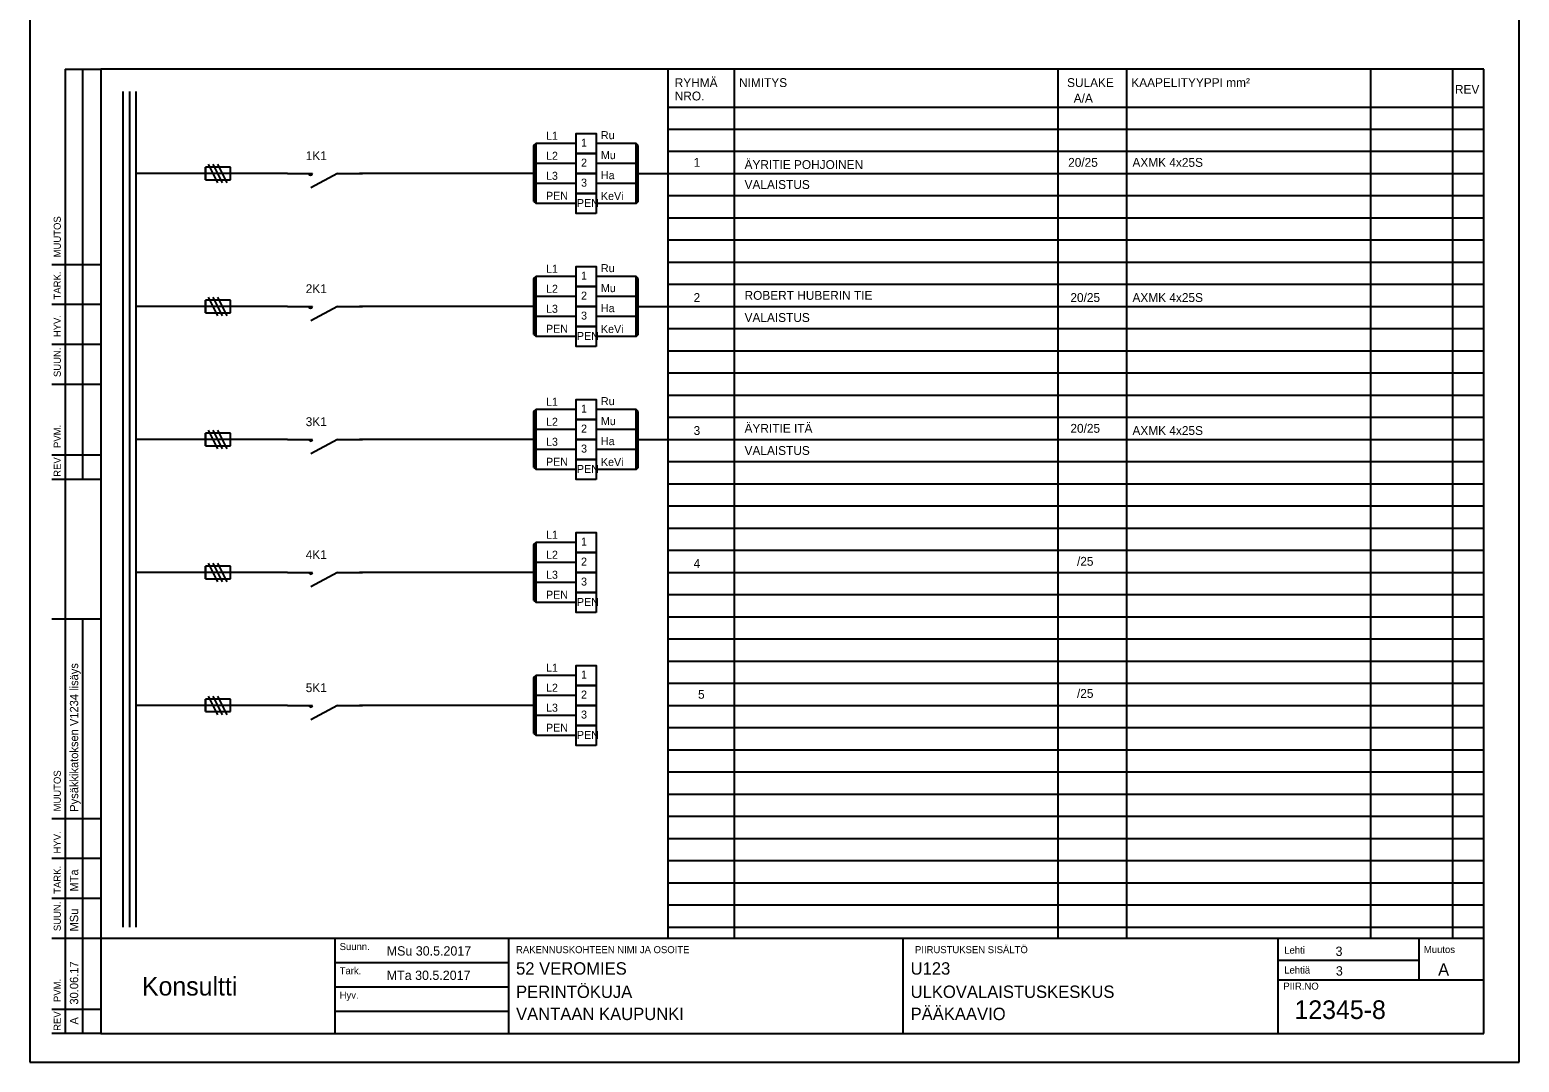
# Model space of a CAD drawing. Extents: x 0 to 420, y -594 to 297.
# Drawn here: x 0 to 420, y -594 to -302.9 of the extents above; entities that cross this region are included whole.
import ezdxf

# ---------------------------------------------------------------- set-up
doc = ezdxf.new("R2010")
doc.units = 0
for name, color, linetype in [('SAH3340_E0', 7, 'Continuous'), ('SK100J', 7, 'Continuous'), ('TEKSTI', 7, 'Continuous')]:
    doc.layers.add(name, color=color, linetype=linetype)

# ---------------------------------------------------------------- blocks, each defined once
blk = doc.blocks.new('taulukko')
for p, q in [((180, 35), (180, 280)), ((198.75, 35), (198.75, 279.96)), ((290, 35), (290, 280)), ((309.38, 35), (309.38, 280)), ((378.12, 35), (378.12, 280)), ((401.25, 35), (401.25, 279.96)), ((30, 38.12), (30, 273.75)), ((180, 269.37), (410, 269.37)), ((180, 256.87), (410, 256.87)), ((180, 244.37), (410, 244.37)), ((180, 231.87), (410, 231.87)), ((180, 219.37), (410, 219.37)), ((180, 206.87), (410, 206.87)), ((180, 194.37), (410, 194.37)), ((180, 181.87), (410, 181.87)), ((180, 169.37), (410, 169.37)), ((180, 156.87), (410, 156.87)), ((180, 144.37), (410, 144.37)), ((180, 131.87), (410, 131.87)), ((180, 119.37), (410, 119.37)), ((180, 106.87), (410, 106.87)), ((180, 94.37), (410, 94.37)), ((180, 81.87), (410, 81.87)), ((180, 69.37), (410, 69.37)), ((180, 56.87), (410, 56.87)), ((180, 44.37), (410, 44.37))]:
    blk.add_line(p, q)
for points in [[(26.25, 273.75), (26.25, 38.12)], [(28.12, 273.75), (28.12, 38.12)], [(180, 263.12), (410, 263.12)], [(180, 250.62), (410, 250.62)], [(180, 238.12), (410, 238.12)], [(180, 225.62), (410, 225.62)], [(180, 213.12), (410, 213.12)], [(180, 200.62), (410, 200.62)], [(180, 188.12), (410, 188.12)], [(180, 175.62), (410, 175.62)], [(180, 163.12), (410, 163.12)], [(180, 150.62), (410, 150.62)], [(180, 138.12), (410, 138.12)], [(180, 125.62), (410, 125.62)], [(180, 113.12), (410, 113.12)], [(180, 100.62), (410, 100.62)], [(180, 88.12), (410, 88.12)], [(180, 75.62), (410, 75.62)], [(180, 63.12), (410, 63.12)], [(180, 50.62), (410, 50.62)], [(180, 38.12), (410, 38.12)]]:
    blk.add_lwpolyline(points)
for s, p in [('RYHMÄ', (181.87, 274.97)), ('NIMITYS', (200, 275)), ('SULAKE', (292.5, 275)), ('KAAPELITYYPPI mm²', (310.62, 275)), ('NRO.', (181.87, 271.22)), ('A/A', (294.38, 270.62)), ('REV', (401.88, 273.09))]:
    blk.add_text(s, height=2.5).set_placement(p)
blk = doc.blocks.new('KSU103P')
for p, q in [((0, 0), (-15, 0)), ((-10, -1.25), (-10, 1.25)), ((-10, 1.25), (-10, -1.25)), ((-5, 1.25), (-10, 1.25)), ((-5, -1.25), (-5, 1.25)), ((-10, -1.25), (-5, -1.25))]:
    blk.add_line(p, q)
at = {"layer": 'SK100J'}
for p, q in [((-7.5, -1.875), (-9.375, 1.875)), ((-6.5625, -1.875), (-8.4375, 1.875)), ((-5.625, -1.875), (-7.5, 1.875))]:
    blk.add_line(p, q, dxfattribs=at)
blk = doc.blocks.new('KKY101P')
for p, q in [((-15, 0), (-10, 0)), ((-5, 0), (-10.36, -2.86)), ((-5, 0), (0, 0))]:
    blk.add_line(p, q)
blk.add_arc((-10.39, 0.06), 0.395, 189.2122, 350.7878)

msp = doc.modelspace()

# ---------------------------------------------------------------- linework, layer by layer
for p, q in [((0, -297), (0, -594)), ((420, -594), (420, -297)), ((10, -314), (10, -585.88)), ((15, -429.62), (15, -314)), ((20, -314), (20, -585.88)), ((410, -314), (20, -314)), ((410, -585.88), (410, -314)), ((15, -585.88), (15, -469)), ((410, -561.5), (410, -509)), ((20, -559), (410, -559)), ((86, -559), (86, -585.88)), ((135, -559), (135, -585.88)), ((246.25, -585.88), (246.25, -559)), ((352, -585.88), (352, -559)), ((391.75, -570.78), (391.75, -559)), ((86, -565.88), (135, -565.88)), ((351.88, -565.25), (391.75, -565.25)), ((351.88, -570.8), (410, -570.8)), ((86, -572.75), (135, -572.75)), ((86, -579.62), (135, -579.62)), ((20, -585.88), (410, -585.88))]:
    msp.add_line(p, q)
for points in [[(10, -314), (20.14, -314)], [(6.25, -369), (20, -369)], [(6.25, -380.25), (20, -380.25)], [(6.25, -391.5), (20, -391.5)], [(6.25, -402.75), (20, -402.75)], [(6.25, -422.75), (20, -422.75)], [(6.25, -429.62), (20.14, -429.62)], [(6.25, -469), (20, -469)], [(6.25, -525.25), (20, -525.25)], [(6.25, -536.5), (20, -536.5)], [(6.25, -547.75), (20, -547.75)], [(6.25, -559), (20, -559)], [(6.25, -579), (20, -579)], [(20, -585.88), (6.25, -585.88)], [(0, -594), (420, -594)]]:
    msp.add_lwpolyline(points)
at = {"layer": 'SAH3340_E0'}
for p, q in [((142.18, -335.48), (142.75, -334.91)), ((142.18, -351.27), (142.18, -335.48)), ((142.75, -351.84), (142.75, -334.91)), ((154.03, -334.91), (142.75, -334.91)), ((170.95, -334.91), (159.67, -334.91)), ((170.95, -351.84), (170.95, -334.91)), ((171.51, -335.48), (170.95, -334.91)), ((171.51, -351.27), (171.51, -335.48)), ((48.12, -343.38), (29.83, -343.38)), ((72.69, -343.38), (63.62, -343.38)), ((142.5, -343.38), (92.96, -343.38)), ((142.18, -341.12), (142.75, -340.55)), ((154.03, -340.55), (142.75, -340.55)), ((142.75, -351.84), (142.75, -340.55)), ((170.95, -340.55), (159.67, -340.55)), ((170.95, -351.84), (170.95, -340.55)), ((171.51, -341.12), (170.95, -340.55)), ((171.51, -343.38), (180, -343.38)), ((154.03, -346.19), (142.75, -346.19)), ((170.95, -346.19), (159.67, -346.19)), ((154.03, -351.84), (142.75, -351.84)), ((170.95, -351.84), (159.67, -351.84)), ((142.18, -372.98), (142.75, -372.41)), ((142.18, -388.77), (142.18, -372.98)), ((142.75, -389.34), (142.75, -372.41)), ((154.03, -372.41), (142.75, -372.41)), ((170.95, -372.41), (159.67, -372.41)), ((170.95, -389.34), (170.95, -372.41)), ((171.51, -372.98), (170.95, -372.41)), ((171.51, -388.77), (171.51, -372.98)), ((48.12, -380.88), (29.83, -380.88)), ((72.69, -380.88), (62.98, -380.88)), ((142.5, -380.88), (92.96, -380.88)), ((142.18, -378.62), (142.75, -378.05)), ((154.03, -378.05), (142.75, -378.05)), ((142.75, -389.34), (142.75, -378.05)), ((170.95, -378.05), (159.67, -378.05)), ((170.95, -389.34), (170.95, -378.05)), ((171.51, -378.62), (170.95, -378.05)), ((171.51, -380.88), (180, -380.88)), ((154.03, -383.69), (142.75, -383.69)), ((170.95, -383.69), (159.67, -383.69)), ((154.03, -389.34), (142.75, -389.34)), ((170.95, -389.34), (159.67, -389.34)), ((142.18, -410.48), (142.75, -409.91)), ((142.18, -426.27), (142.18, -410.48)), ((142.75, -426.84), (142.75, -409.91)), ((154.03, -409.91), (142.75, -409.91)), ((170.95, -409.91), (159.67, -409.91)), ((170.95, -426.84), (170.95, -409.91)), ((171.51, -410.48), (170.95, -409.91)), ((171.51, -426.27), (171.51, -410.48)), ((142.18, -416.12), (142.75, -415.55)), ((154.03, -415.55), (142.75, -415.55)), ((142.75, -426.84), (142.75, -415.55)), ((170.95, -415.55), (159.67, -415.55)), ((170.95, -426.84), (170.95, -415.55)), ((171.51, -416.12), (170.95, -415.55)), ((48.12, -418.38), (29.83, -418.38)), ((72.69, -418.38), (62.98, -418.38)), ((142.5, -418.38), (92.96, -418.38)), ((171.51, -418.38), (180, -418.38)), ((154.03, -421.19), (142.75, -421.19)), ((170.95, -421.19), (159.67, -421.19)), ((154.03, -426.84), (142.75, -426.84)), ((170.95, -426.84), (159.67, -426.84)), ((142.18, -447.98), (142.75, -447.41)), ((142.18, -463.77), (142.18, -447.98)), ((142.75, -464.34), (142.75, -447.41)), ((154.03, -447.41), (142.75, -447.41)), ((142.18, -453.62), (142.75, -453.05)), ((154.03, -453.05), (142.75, -453.05)), ((142.75, -464.34), (142.75, -453.05)), ((48.12, -455.88), (29.83, -455.88)), ((72.69, -455.88), (62.98, -455.88)), ((142.5, -455.88), (92.96, -455.88)), ((154.03, -458.69), (142.75, -458.69)), ((154.03, -464.34), (142.75, -464.34)), ((142.18, -485.48), (142.75, -484.92)), ((142.18, -501.27), (142.18, -485.48)), ((142.75, -501.84), (142.75, -484.92)), ((154.03, -484.92), (142.75, -484.92)), ((142.18, -491.12), (142.75, -490.56)), ((154.03, -490.56), (142.75, -490.56)), ((142.75, -501.84), (142.75, -490.56)), ((48.12, -493.38), (29.83, -493.38)), ((72.69, -493.38), (62.98, -493.38)), ((142.5, -493.38), (92.96, -493.38)), ((154.03, -496.2), (142.75, -496.2)), ((154.03, -501.84), (142.75, -501.84))]:
    msp.add_line(p, q, dxfattribs=at)
for points in [[(142.18, -351.27), (142.75, -351.84), (142.75, -334.91), (142.18, -335.48), (142.18, -351.27)], [(171.51, -335.48), (170.95, -334.91), (170.95, -351.84), (171.51, -351.27), (171.51, -335.48)], [(142.18, -388.77), (142.75, -389.34), (142.75, -372.41), (142.18, -372.98), (142.18, -388.77)], [(171.51, -372.98), (170.95, -372.41), (170.95, -389.34), (171.51, -388.77), (171.51, -372.98)], [(142.18, -426.27), (142.75, -426.84), (142.75, -409.91), (142.18, -410.48), (142.18, -426.27)], [(171.51, -410.48), (170.95, -409.91), (170.95, -426.84), (171.51, -426.27), (171.51, -410.48)], [(142.18, -463.77), (142.75, -464.34), (142.75, -447.41), (142.18, -447.98), (142.18, -463.77)], [(142.18, -501.27), (142.75, -501.84), (142.75, -484.92), (142.18, -485.48), (142.18, -501.27)]]:
    msp.add_lwpolyline(points, dxfattribs=at)
for points in [[(159.67, -337.73), (154.03, -337.73), (154.03, -332.09), (159.67, -332.09)], [(159.67, -343.38), (154.03, -343.38), (154.03, -337.73), (159.67, -337.73)], [(159.67, -349.01), (154.03, -349.01), (154.03, -343.38), (159.67, -343.38)], [(159.67, -354.65), (154.03, -354.65), (154.03, -349.01), (159.67, -349.01)], [(159.67, -375.23), (154.03, -375.23), (154.03, -369.59), (159.67, -369.59)], [(159.67, -380.88), (154.03, -380.88), (154.03, -375.23), (159.67, -375.23)], [(159.67, -386.51), (154.03, -386.51), (154.03, -380.88), (159.67, -380.88)], [(159.67, -392.15), (154.03, -392.15), (154.03, -386.51), (159.67, -386.51)], [(159.67, -412.73), (154.03, -412.73), (154.03, -407.09), (159.67, -407.09)], [(159.67, -418.38), (154.03, -418.38), (154.03, -412.73), (159.67, -412.73)], [(159.67, -424.01), (154.03, -424.01), (154.03, -418.38), (159.67, -418.38)], [(159.67, -429.65), (154.03, -429.65), (154.03, -424.01), (159.67, -424.01)], [(159.67, -450.23), (154.03, -450.23), (154.03, -444.59), (159.67, -444.59)], [(159.67, -455.88), (154.03, -455.88), (154.03, -450.23), (159.67, -450.23)], [(159.67, -461.51), (154.03, -461.51), (154.03, -455.88), (159.67, -455.88)], [(159.67, -467.15), (154.03, -467.15), (154.03, -461.51), (159.67, -461.51)], [(159.67, -487.74), (154.03, -487.74), (154.03, -482.1), (159.67, -482.1)], [(159.67, -493.38), (154.03, -493.38), (154.03, -487.74), (159.67, -487.74)], [(159.67, -499.02), (154.03, -499.02), (154.03, -493.38), (159.67, -493.38)], [(159.67, -504.66), (154.03, -504.66), (154.03, -499.02), (159.67, -499.02)]]:
    msp.add_lwpolyline(points, close=True, dxfattribs=at)

# ---------------------------------------------------------------- block references
msp.add_blockref('taulukko', (0, -594))
at = {"layer": 'SAH3340_E0', "xscale": 1.41, "yscale": 1.41}
for name, p in [('KSU103P', (63.62, -343.38)), ('KKY101P', (93.84, -343.38)), ('KSU103P', (63.62, -380.88)), ('KKY101P', (93.84, -380.88)), ('KSU103P', (63.62, -418.38)), ('KKY101P', (93.84, -418.38)), ('KSU103P', (63.62, -455.88)), ('KKY101P', (93.84, -455.88)), ('KSU103P', (63.62, -493.38)), ('KKY101P', (93.84, -493.38))]:
    msp.add_blockref(name, p, dxfattribs=at)

# ---------------------------------------------------------------- texts
for s, height, p in [('1K1', 2.5, (77.81, -339.62)), ('1', 2.5, (187.19, -341.5)), ('ÄYRITIE POHJOINEN', 2.5, (201.56, -342.12)), ('20/25', 2.5, (292.81, -341.5)), ('AXMK 4x25S', 2.5, (310.94, -341.5)), ('VALAISTUS', 2.5, (201.56, -347.75)), ('2K1', 2.5, (77.81, -377.12)), ('2', 2.5, (187.19, -379.62)), ('ROBERT HUBERIN TIE', 2.5, (201.56, -379)), ('20/25', 2.5, (293.44, -379.62)), ('AXMK 4x25S', 2.5, (310.94, -379.62)), ('VALAISTUS', 2.5, (201.56, -385.25)), ('3K1', 2.5, (77.81, -414.62)), ('3', 2.5, (187.19, -417.12)), ('ÄYRITIE ITÄ', 2.5, (201.56, -416.5)), ('20/25', 2.5, (293.44, -416.5)), ('AXMK 4x25S', 2.5, (310.94, -417.12)), ('VALAISTUS', 2.5, (201.56, -422.75)), ('4K1', 2.5, (77.81, -452.12)), ('4', 2.5, (187.19, -454.62)), ('  /25', 2.5, (293.44, -454)), ('5K1', 2.5, (77.81, -489.63)), ('5', 2.5, (188.44, -491.5)), ('  /25', 2.5, (293.44, -491.25)), ('Suunn.', 2, (87.38, -562.38)), ('MSu 30.5.2017', 2.625, (100.66, -563.92)), ('RAKENNUSKOHTEEN NIMI JA OSOITE', 2, (137.12, -563.25)), ('PIIRUSTUKSEN SISÄLTÖ', 2, (249.62, -563.25)), ('Lehti', 2, (353.75, -563.38)), ('3', 2.62, (368.21, -564.02)), ('Muutos', 2, (393.12, -563.21)), ('52 VEROMIES', 3.5, (137.12, -569.31)), ('U123', 3.5, (248.38, -569.31)), ('Lehtiä', 2, (353.75, -569)), ('3', 2.62, (368.31, -569.56)), ('A', 3.5, (397.12, -569.62)), ('Konsultti', 5.25, (31.62, -575.19)), ('Tark.', 2, (87.38, -569.2)), ('MTa 30.5.2017', 2.625, (100.66, -570.8)), ('Hyv.', 2, (87.38, -576.07)), ('PERINTÖKUJA', 3.5, (137.12, -575.88)), ('ULKOVALAISTUSKESKUS', 3.5, (248.38, -575.88)), ('PIIR.NO', 2, (353.5, -573.55)), ('VANTAAN KAUPUNKI', 3.5, (137.12, -582.12)), ('PÄÄKAAVIO', 3.5, (248.38, -582.12)), ('12345-8', 5.25, (356.62, -581.81))]:
    msp.add_text(s, height=height).set_placement(p)
for s, p in [('MUUTOS', (8.75, -367.03)), ('TARK.', (8.75, -378.9)), ('HYV.', (8.75, -389.53)), ('SUUN.', (8.75, -400.78)), ('PVM.', (8.75, -420.78)), ('REV', (8.75, -428.9)), ('MUUTOS', (8.75, -523.28)), ('HYV.', (8.75, -535.15)), ('TARK.', (8.75, -546.5)), ('SUUN.', (8.75, -557.03)), ('PVM.', (8.75, -577.03)), ('REV', (8.75, -585.15))]:
    msp.add_text(s, height=2, rotation=90).set_placement(p)
at = {"layer": 'SAH3340_E0'}
for s, height, p in [('L1', 2.256, (145.57, -333.88)), ('Ru', 2.256, (161.06, -333.7)), ('1', 2.26, (155.45, -335.81)), ('L2', 2.256, (145.57, -339.52)), ('2', 2.26, (155.45, -341.45)), ('Mu', 2.256, (161.06, -339.34)), ('L3', 2.256, (145.57, -345.16)), ('Ha', 2.256, (161.06, -344.98)), ('PEN', 2.256, (145.57, -350.8)), ('3', 2.26, (155.45, -347.09)), ('KeVi', 2.256, (161.06, -350.86)), ('PEN', 2.256, (154.29, -352.84)), ('L1', 2.256, (145.57, -371.38)), ('Ru', 2.256, (161.06, -371.2)), ('1', 2.26, (155.45, -373.31)), ('L2', 2.256, (145.57, -377.02)), ('2', 2.26, (155.45, -378.95)), ('Mu', 2.256, (161.06, -376.84)), ('L3', 2.256, (145.57, -382.66)), ('Ha', 2.256, (161.06, -382.48)), ('PEN', 2.256, (145.57, -388.3)), ('3', 2.26, (155.45, -384.59)), ('KeVi', 2.256, (161.06, -388.36)), ('PEN', 2.256, (154.29, -390.34)), ('L1', 2.256, (145.57, -408.88)), ('Ru', 2.256, (161.06, -408.7)), ('1', 2.26, (155.45, -410.81)), ('L2', 2.256, (145.57, -414.52)), ('2', 2.26, (155.45, -416.45)), ('Mu', 2.256, (161.06, -414.34)), ('L3', 2.256, (145.57, -420.16)), ('3', 2.26, (155.45, -422.09)), ('Ha', 2.256, (161.06, -419.98)), ('PEN', 2.256, (145.57, -425.8)), ('KeVi', 2.256, (161.06, -425.86)), ('PEN', 2.256, (154.29, -427.84)), ('L1', 2.256, (145.57, -446.38)), ('1', 2.26, (155.45, -448.31)), ('L2', 2.256, (145.57, -452.02)), ('2', 2.26, (155.45, -453.95)), ('L3', 2.256, (145.57, -457.66)), ('3', 2.26, (155.45, -459.59)), ('PEN', 2.256, (145.57, -463.3)), ('PEN', 2.256, (154.29, -465.34)), ('L1', 2.256, (145.57, -483.88)), ('1', 2.26, (155.45, -485.81)), ('L2', 2.256, (145.57, -489.52)), ('2', 2.26, (155.45, -491.45)), ('L3', 2.256, (145.57, -495.16)), ('3', 2.26, (155.45, -497.09)), ('PEN', 2.256, (145.57, -500.8)), ('PEN', 2.256, (154.29, -502.84))]:
    msp.add_text(s, height=height, dxfattribs=at).set_placement(p)
at = {"layer": 'TEKSTI'}
for s, p in [('Pysäkkikatoksen V1234 lisäys', (13.65, -523.38)), ('MTa', (13.65, -545.88)), ('MSu', (13.65, -557.12)), ('30.06.17', (13.65, -577.75)), ('A', (13.65, -583.38))]:
    msp.add_text(s, height=2.34, rotation=90, dxfattribs=at).set_placement(p)

doc.saveas('drawing.dxf')
